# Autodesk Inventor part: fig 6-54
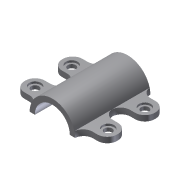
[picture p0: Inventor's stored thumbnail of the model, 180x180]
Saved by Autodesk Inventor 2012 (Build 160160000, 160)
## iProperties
Created: 2004-05
Part Number: fig 6-54
Document SubType Name: Modeling
Designer: CADCIM Technologies
Manufacturer: Standard
Standards Organization: Custom
Density: 1 g/cm^3
Material: Default
Author: CADCIM Technologies
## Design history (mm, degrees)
node "Sketch1"
sketch "Sketch2"
  geometry: L1 (23.378, 0)-(17.996, 0); L2 (-17.996, 0)-(-23.378, 0); A1 r 23.378 centre (0, 0) between (23.378, 0) and (-23.378, 0); A2 r 17.996 centre (0, 0) between (17.996, 0) and (-17.996, 0)
  constraints: 4 end point, 4 point on circle, 2 centre point, 1 collinear, 1 horizontal
extrude "Extrusion1" new body sketch "Sketch2" stored distance "d0" = 38.75; taper "d1" = 0 deg
sketch "Sketch3"
  geometry: L1 (23.378, 0)-(17.996, 0); L2 (-17.996, 0)-(-23.378, 0) reference; L3 (-23.378, 0)-(-47.662, 0); L4 (-47.662, 0)-(-47.662, 5.722); L5 (-47.662, 5.722)-(-22.667, 5.722); A1 r 17.996 centre (0, 0) between (17.996, 0) and (-17.996, 0) reference; A2 r 23.378 centre (0, 0) between (23.378, 0) and (-23.378, 0) reference; 1 further point
  constraints: 10 end point, 5 point on circle, 2 centre point, 1 collinear, 1 horizontal, 1 midpoint, 1 parallel, 1 perpendicular, 3 other
extrude "Extrusion2" join sketch "Sketch3" stored distance "d2" = 21; taper "d3" = 0 deg
fillet "Fillet1" dims "d4" = 10
hole "Hole1" diameter "d7" = 8; stored, may be unused: countersink angle "d11" = 90 deg, drill point angle "d13" = 118 deg; dims "d5" = 10, "d6" = 10, "d8" = 6, "d9" = 12, "d10" = 2, "d12" = 12
fillet "Fillet2" dims "d14" = 9.5
mirror "Mirror1"
mirror "Mirror2"
body "Solid1"
